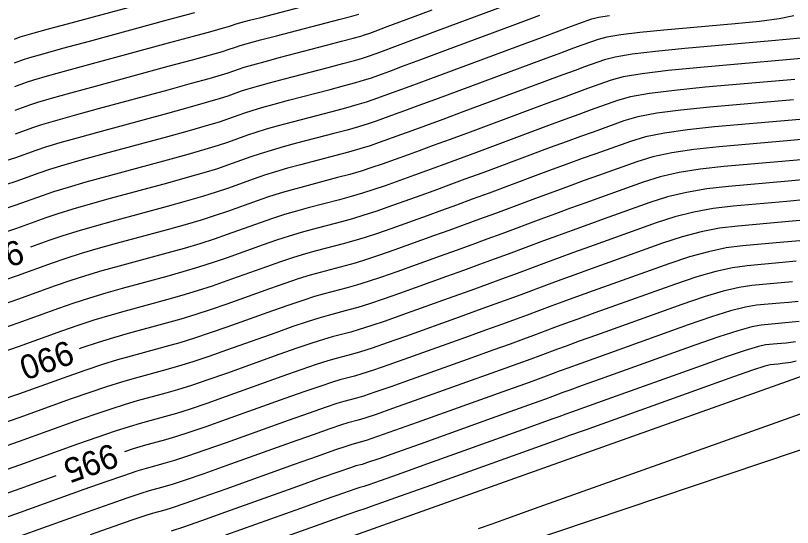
# Model space of a CAD drawing. Extents: x 2175772 to 2185556, y 721391 to 722853.
# Drawn here: x 2179071.3 to 2179161.1, y 721918.3 to 721977.4 of the extents above; entities that cross this region are included whole.
import ezdxf

# ---------------------------------------------------------------- set-up
doc = ezdxf.new("R2010")
doc.units = 0
for name, color, linetype in [('DT_X_Contour_Major', 7, 'Continuous'), ('DT_X_Contour_Minor', 7, 'Continuous'), ('DT_X_TIN_Hull', 7, 'Continuous')]:
    doc.layers.add(name, color=color, linetype=linetype)

msp = doc.modelspace()

# ---------------------------------------------------------------- linework, layer by layer
at = {"layer": 'DT_X_Contour_Major'}
for points in [[(2179071.294, 721963.77), (2179073.312, 721964.492), (2179074.353, 721964.832), (2179075.959, 721965.309), (2179078.132, 721965.922), (2179080.872, 721966.673), (2179088.932, 721968.858), (2179091.632, 721969.595), (2179093.69, 721970.167), (2179095.103, 721970.575), (2179095.873, 721970.818), (2179097.069, 721971.246), (2179097.71, 721971.451), (2179098.733, 721971.746), (2179100.141, 721972.129), (2179101.932, 721972.603), (2179107.219, 721973.983), (2179108.981, 721974.447), (2179110.304, 721974.8), (2179111.187, 721975.044), (2179111.629, 721975.179), (2179112.223, 721975.391), (2179112.842, 721975.619), (2179114.252, 721976.141), (2179116.453, 721976.959), (2179119.446, 721978.073)], [(2179162.018, 721974.797), (2179158.678, 721974.486), (2179148.637, 721973.601), (2179145.233, 721973.272), (2179142.554, 721972.948), (2179140.599, 721972.629), (2179139.368, 721972.315), (2179137.052, 721971.486), (2179135.964, 721971.092), (2179134.44, 721970.532), (2179132.479, 721969.807), (2179130.08, 721968.916), (2179123.102, 721966.319), (2179120.69, 721965.423), (2179118.689, 721964.683), (2179117.098, 721964.1), (2179115.917, 721963.673), (2179113.317, 721962.741), (2179112.272, 721962.386), (2179111.088, 721962.018), (2179109.765, 721961.637), (2179108.303, 721961.243), (2179104.218, 721960.176), (2179102.734, 721959.775), (2179101.346, 721959.37), (2179100.054, 721958.963), (2179098.858, 721958.554), (2179095.795, 721957.457), (2179094.498, 721957.018), (2179092.905, 721956.524), (2179091.014, 721955.974), (2179088.827, 721955.369), (2179082.598, 721953.68), (2179080.381, 721953.064), (2179078.401, 721952.482), (2179076.659, 721951.935), (2179075.154, 721951.421), (2179073.027, 721950.66)], [(2179163.731, 721963.251), (2179160.871, 721962.993), (2179152.599, 721962.264), (2179149.678, 721961.951), (2179147.119, 721961.558), (2179144.922, 721961.085), (2179143.087, 721960.533), (2179138.677, 721958.954), (2179136.999, 721958.35), (2179135.273, 721957.722), (2179133.5, 721957.071), (2179131.678, 721956.396), (2179126.757, 721954.565), (2179124.927, 721953.886), (2179123.125, 721953.225), (2179121.354, 721952.581), (2179119.611, 721951.954), (2179115.004, 721950.304), (2179113.357, 721949.727), (2179111.872, 721949.235), (2179110.549, 721948.827), (2179109.387, 721948.502), (2179106.505, 721947.75), (2179105.328, 721947.42), (2179103.959, 721946.995), (2179102.399, 721946.476), (2179100.646, 721945.861), (2179095.717, 721944.097), (2179093.894, 721943.462), (2179092.12, 721942.881), (2179090.396, 721942.353), (2179088.722, 721941.879), (2179084.324, 721940.687), (2179082.629, 721940.206), (2179080.842, 721939.656), (2179078.964, 721939.037), (2179078.651, 721938.928)], [(2179161.915, 721951.409), (2179160.094, 721951.239), (2179155.288, 721950.815), (2179153.406, 721950.567), (2179151.365, 721950.14), (2179149.165, 721949.534), (2179146.805, 721948.75), (2179140.302, 721946.422), (2179138.033, 721945.608), (2179136.107, 721944.912), (2179134.521, 721944.335), (2179133.276, 721943.876), (2179130.413, 721942.811), (2179129.163, 721942.35), (2179127.562, 721941.767), (2179125.609, 721941.062), (2179123.305, 721940.235), (2179116.691, 721937.867), (2179114.442, 721937.069), (2179112.656, 721936.452), (2179111.332, 721936.017), (2179110.471, 721935.762), (2179108.791, 721935.323), (2179107.922, 721935.065), (2179106.572, 721934.62), (2179104.743, 721933.988), (2179102.435, 721933.169), (2179095.639, 721930.736), (2179093.289, 721929.905), (2179091.335, 721929.237), (2179089.778, 721928.732), (2179088.617, 721928.39), (2179086.05, 721927.694), (2179084.877, 721927.347), (2179083.898, 721927.029)], [(2179161.41, 721939.711), (2179160.871, 721939.645), (2179160.342, 721939.585), (2179159.824, 721939.531), (2179159.316, 721939.484), (2179157.976, 721939.365), (2179157.134, 721939.182), (2179155.611, 721938.722), (2179153.407, 721937.984), (2179150.524, 721936.968), (2179139.068, 721932.866), (2179135.542, 721931.599), (2179134.875, 721931.356), (2179134.069, 721931.056), (2179133.4, 721930.813), (2179129.865, 721929.543), (2179118.378, 721925.43), (2179115.527, 721924.411), (2179113.44, 721923.67), (2179112.116, 721923.207), (2179111.555, 721923.021), (2179111.078, 721922.896), (2179110.515, 721922.71), (2179109.185, 721922.245), (2179107.088, 721921.5), (2179104.223, 721920.477), (2179095.561, 721917.376)], [(2179075.97, 721924.253), (2179071.784, 721922.755), (2179069.361, 721921.896)]]:
    msp.add_lwpolyline(points, dxfattribs=at)
at = {"layer": 'DT_X_Contour_Minor'}
for points in [[(2179071.163, 721974.707), (2179071.84, 721974.949), (2179072.372, 721975.113), (2179073.461, 721975.422), (2179075.108, 721975.877), (2179077.312, 721976.477), (2179088.895, 721979.617)], [(2179070.229, 721960.668), (2179071.326, 721961.035), (2179073.681, 721961.878), (2179074.814, 721962.252), (2179076.448, 721962.743), (2179078.582, 721963.351), (2179081.217, 721964.074), (2179088.911, 721966.16), (2179091.509, 721966.871), (2179093.533, 721967.439), (2179094.982, 721967.864), (2179095.858, 721968.146), (2179097.427, 721968.707), (2179098.179, 721968.954), (2179099.256, 721969.271), (2179100.659, 721969.659), (2179102.389, 721970.117), (2179107.435, 721971.435), (2179109.138, 721971.885), (2179110.461, 721972.244), (2179111.404, 721972.512), (2179111.967, 721972.691), (2179112.962, 721973.048), (2179113.693, 721973.315), (2179115.139, 721973.85), (2179120.177, 721975.722), (2179128.802, 721978.932)], [(2179071.228, 721969.238), (2179072.576, 721969.721), (2179073.43, 721969.991), (2179074.983, 721970.439), (2179077.233, 721971.066), (2179080.181, 721971.87), (2179088.974, 721974.254), (2179091.88, 721975.043), (2179094.003, 721975.625), (2179095.345, 721975.997), (2179095.905, 721976.162), (2179096.354, 721976.323), (2179096.686, 721976.424), (2179097.346, 721976.606), (2179098.332, 721976.87), (2179099.646, 721977.215), (2179106.542, 721979.016)], [(2179161.241, 721977.404), (2179159.522, 721977.055), (2179157.256, 721976.738), (2179154.444, 721976.451), (2179146.218, 721975.725), (2179143.43, 721975.455), (2179141.235, 721975.19), (2179139.633, 721974.929), (2179138.625, 721974.672), (2179136.727, 721973.992), (2179135.757, 721973.64), (2179134.273, 721973.094), (2179132.274, 721972.354), (2179119.843, 721967.73), (2179117.801, 721966.975), (2179116.247, 721966.404), (2179115.178, 721966.016), (2179112.979, 721965.229), (2179112.055, 721964.917), (2179110.931, 721964.574), (2179109.608, 721964.199), (2179108.086, 721963.791), (2179103.761, 721962.661), (2179102.216, 721962.246), (2179100.824, 721961.845), (2179099.585, 721961.461), (2179098.5, 721961.092), (2179095.811, 721960.129), (2179094.619, 721959.73), (2179093.062, 721959.253), (2179091.138, 721958.698), (2179088.848, 721958.066), (2179082.253, 721956.279), (2179079.931, 721955.636), (2179077.913, 721955.047), (2179076.197, 721954.514), (2179074.785, 721954.036), (2179071.424, 721952.833), (2179070.043, 721952.36)], [(2179070.105, 721955.129), (2179071.392, 721955.567), (2179074.417, 721956.65), (2179075.736, 721957.094), (2179077.424, 721957.613), (2179079.481, 721958.207), (2179081.907, 721958.877), (2179088.869, 721960.764), (2179091.261, 721961.422), (2179093.219, 721961.981), (2179094.74, 721962.441), (2179095.827, 721962.801), (2179098.142, 721963.631), (2179099.116, 721963.959), (2179100.301, 721964.321), (2179101.697, 721964.717), (2179103.304, 721965.147), (2179107.869, 721966.339), (2179109.451, 721966.761), (2179110.774, 721967.131), (2179111.838, 721967.449), (2179112.642, 721967.716), (2179114.44, 721968.36), (2179115.395, 721968.707), (2179116.914, 721969.267), (2179118.995, 721970.038), (2179129.441, 721973.924), (2179132.07, 721974.901), (2179134.107, 721975.656), (2179135.55, 721976.189), (2179136.402, 721976.498), (2179137.881, 721977.028), (2179138.667, 721977.228), (2179139.915, 721977.432)], [(2179070.167, 721957.899), (2179071.359, 721958.301), (2179074.049, 721959.264), (2179075.275, 721959.673), (2179076.936, 721960.178), (2179079.032, 721960.779), (2179081.562, 721961.476), (2179088.89, 721963.462), (2179091.385, 721964.147), (2179093.376, 721964.71), (2179094.861, 721965.152), (2179095.842, 721965.474), (2179097.785, 721966.169), (2179098.647, 721966.456), (2179099.779, 721966.796), (2179101.178, 721967.188), (2179102.846, 721967.632), (2179107.652, 721968.887), (2179109.295, 721969.323), (2179110.618, 721969.687), (2179111.621, 721969.981), (2179112.304, 721970.204), (2179113.701, 721970.704), (2179114.544, 721971.011), (2179116.026, 721971.558), (2179118.148, 721972.345), (2179120.908, 721973.371), (2179129.121, 721976.428), (2179131.866, 721977.448)], [(2179071.195, 721971.973), (2179072.208, 721972.335), (2179072.969, 721972.57), (2179074.494, 721973.004), (2179076.783, 721973.637), (2179079.836, 721974.469), (2179088.994, 721976.952), (2179092.003, 721977.768)], [(2179071.261, 721966.504), (2179072.944, 721967.107), (2179073.892, 721967.411), (2179075.471, 721967.874), (2179077.683, 721968.494), (2179080.526, 721969.272), (2179088.953, 721971.556), (2179091.756, 721972.319), (2179093.846, 721972.896), (2179095.224, 721973.286), (2179095.889, 721973.49), (2179096.712, 721973.784), (2179097.241, 721973.949), (2179098.211, 721974.221), (2179099.622, 721974.6), (2179101.474, 721975.088), (2179108.825, 721977.008), (2179110.147, 721977.357), (2179110.97, 721977.576)], [(2179165.129, 721972.718), (2179150.448, 721971.424), (2179146.695, 721971.058), (2179143.722, 721970.692), (2179141.527, 721970.326), (2179140.112, 721969.959), (2179137.377, 721968.979), (2179136.171, 721968.543), (2179134.607, 721967.97), (2179132.683, 721967.26), (2179130.4, 721966.412), (2179123.833, 721963.968), (2179121.537, 721963.116), (2179119.576, 721962.392), (2179117.949, 721961.796), (2179116.656, 721961.329), (2179113.654, 721960.254), (2179112.489, 721959.854), (2179111.245, 721959.461), (2179109.922, 721959.075), (2179108.52, 721958.695), (2179104.676, 721957.691), (2179103.253, 721957.304), (2179101.869, 721956.895), (2179100.523, 721956.466), (2179099.216, 721956.015), (2179095.78, 721954.785), (2179094.378, 721954.307), (2179092.748, 721953.795), (2179090.891, 721953.25), (2179088.806, 721952.671), (2179082.943, 721951.081), (2179080.83, 721950.492), (2179078.889, 721949.917), (2179077.12, 721949.355), (2179075.522, 721948.807), (2179071.49, 721947.364), (2179069.919, 721946.821)], [(2179161.338, 721970.046), (2179150.986, 721969.134), (2179147.441, 721968.781), (2179144.571, 721968.409), (2179142.376, 721968.016), (2179140.856, 721967.602), (2179137.702, 721966.473), (2179136.378, 721965.995), (2179134.773, 721965.408), (2179132.887, 721964.712), (2179130.719, 721963.908), (2179124.564, 721961.617), (2179122.385, 721960.808), (2179120.463, 721960.1), (2179118.8, 721959.492), (2179117.395, 721958.985), (2179113.992, 721957.766), (2179112.706, 721957.322), (2179111.402, 721956.905), (2179110.078, 721956.513), (2179108.736, 721956.147), (2179105.133, 721955.205), (2179103.772, 721954.833), (2179102.392, 721954.42), (2179100.992, 721953.968), (2179099.573, 721953.477), (2179095.764, 721952.113), (2179094.257, 721951.596), (2179092.591, 721951.067), (2179090.767, 721950.526), (2179088.785, 721949.973), (2179083.288, 721948.483), (2179081.28, 721947.921), (2179079.378, 721947.352), (2179077.581, 721946.776), (2179075.89, 721946.193), (2179071.522, 721944.63), (2179069.857, 721944.052)], [(2179161.183, 721967.695), (2179151.523, 721966.844), (2179148.186, 721966.505), (2179145.42, 721966.125), (2179143.224, 721965.705), (2179141.599, 721965.246), (2179138.027, 721963.967), (2179136.585, 721963.447), (2179134.94, 721962.846), (2179133.091, 721962.165), (2179131.039, 721961.404), (2179125.295, 721959.266), (2179123.232, 721958.501), (2179121.351, 721957.808), (2179119.651, 721957.189), (2179118.134, 721956.641), (2179114.329, 721955.279), (2179112.923, 721954.791), (2179111.558, 721954.348), (2179110.235, 721953.951), (2179108.953, 721953.598), (2179105.59, 721952.72), (2179104.291, 721952.362), (2179102.914, 721951.945), (2179101.461, 721951.471), (2179099.931, 721950.938), (2179095.748, 721949.441), (2179094.136, 721948.884), (2179092.434, 721948.338), (2179090.643, 721947.801), (2179088.764, 721947.275), (2179083.633, 721945.884), (2179081.73, 721945.349), (2179079.866, 721944.786), (2179078.042, 721944.196), (2179076.258, 721943.579), (2179071.555, 721941.895), (2179069.795, 721941.282)], [(2179164.08, 721965.618), (2179161.027, 721965.344), (2179152.061, 721964.554), (2179148.932, 721964.228), (2179146.269, 721963.841), (2179144.073, 721963.395), (2179142.343, 721962.889), (2179138.352, 721961.46), (2179136.792, 721960.898), (2179135.107, 721960.284), (2179133.295, 721959.618), (2179131.359, 721958.9), (2179126.026, 721956.915), (2179124.079, 721956.194), (2179122.238, 721955.517), (2179120.502, 721954.885), (2179118.872, 721954.298), (2179114.666, 721952.792), (2179113.14, 721952.259), (2179111.715, 721951.791), (2179110.392, 721951.389), (2179109.17, 721951.05), (2179106.047, 721950.235), (2179104.809, 721949.891), (2179103.437, 721949.47), (2179101.93, 721948.973), (2179100.289, 721948.4), (2179095.733, 721946.769), (2179094.015, 721946.173), (2179092.277, 721945.609), (2179090.52, 721945.077), (2179088.743, 721944.577), (2179083.979, 721943.286), (2179082.179, 721942.777), (2179080.354, 721942.221), (2179078.503, 721941.617), (2179076.627, 721940.964), (2179071.588, 721939.161), (2179069.733, 721938.513)], [(2179163.381, 721960.885), (2179160.716, 721960.642), (2179153.137, 721959.974), (2179150.423, 721959.674), (2179147.968, 721959.274), (2179145.77, 721958.775), (2179143.83, 721958.176), (2179139.002, 721956.447), (2179137.206, 721955.801), (2179135.44, 721955.16), (2179133.704, 721954.524), (2179131.998, 721953.892), (2179127.488, 721952.214), (2179125.774, 721951.579), (2179124.013, 721950.934), (2179122.205, 721950.277), (2179120.35, 721949.61), (2179115.341, 721947.817), (2179113.574, 721947.196), (2179112.029, 721946.678), (2179110.705, 721946.265), (2179109.604, 721945.954), (2179106.962, 721945.264), (2179105.847, 721944.949), (2179104.482, 721944.52), (2179102.868, 721943.978), (2179101.004, 721943.323), (2179095.702, 721941.425), (2179093.773, 721940.751), (2179091.963, 721940.152), (2179090.272, 721939.629), (2179088.701, 721939.181), (2179084.669, 721938.088), (2179083.079, 721937.634), (2179081.331, 721937.09), (2179079.426, 721936.458), (2179077.363, 721935.736), (2179071.653, 721933.692), (2179069.609, 721932.974)], [(2179163.032, 721958.518), (2179160.56, 721958.291), (2179153.674, 721957.684), (2179151.169, 721957.397), (2179148.817, 721956.991), (2179146.619, 721956.465), (2179144.574, 721955.82), (2179139.327, 721953.941), (2179137.413, 721953.253), (2179135.607, 721952.598), (2179133.908, 721951.976), (2179132.318, 721951.388), (2179128.22, 721949.863), (2179126.621, 721949.272), (2179124.9, 721948.642), (2179123.056, 721947.973), (2179121.089, 721947.266), (2179115.679, 721945.329), (2179113.791, 721944.664), (2179112.186, 721944.122), (2179110.862, 721943.703), (2179109.821, 721943.406), (2179107.419, 721942.779), (2179106.365, 721942.478), (2179105.005, 721942.045), (2179103.337, 721941.481), (2179101.362, 721940.785), (2179095.686, 721938.753), (2179093.652, 721938.039), (2179091.806, 721937.423), (2179090.149, 721936.905), (2179088.68, 721936.483), (2179085.014, 721935.49), (2179083.528, 721935.062), (2179081.819, 721934.525), (2179079.887, 721933.878), (2179077.731, 721933.122), (2179071.686, 721930.958), (2179069.547, 721930.205)], [(2179162.682, 721956.151), (2179160.405, 721955.941), (2179154.212, 721955.395), (2179151.915, 721955.12), (2179149.666, 721954.707), (2179147.467, 721954.155), (2179145.318, 721953.463), (2179139.652, 721951.435), (2179137.62, 721950.705), (2179135.773, 721950.036), (2179134.112, 721949.429), (2179132.637, 721948.884), (2179128.951, 721947.512), (2179127.469, 721946.964), (2179125.787, 721946.35), (2179123.907, 721945.67), (2179121.827, 721944.923), (2179116.016, 721942.842), (2179114.008, 721942.133), (2179112.342, 721941.565), (2179111.019, 721941.141), (2179110.037, 721940.858), (2179107.877, 721940.294), (2179106.884, 721940.007), (2179105.527, 721939.57), (2179103.806, 721938.983), (2179101.719, 721938.246), (2179095.67, 721936.081), (2179093.531, 721935.328), (2179091.649, 721934.695), (2179090.025, 721934.18), (2179088.659, 721933.786), (2179085.36, 721932.891), (2179083.978, 721932.491), (2179082.307, 721931.96), (2179080.348, 721931.299), (2179078.099, 721930.507), (2179071.719, 721928.224), (2179069.485, 721927.435)], [(2179162.333, 721953.784), (2179160.249, 721953.59), (2179154.75, 721953.105), (2179152.66, 721952.843), (2179150.515, 721952.423), (2179148.316, 721951.845), (2179146.062, 721951.107), (2179139.977, 721948.928), (2179137.827, 721948.156), (2179135.94, 721947.474), (2179134.317, 721946.882), (2179132.957, 721946.38), (2179129.682, 721945.161), (2179128.316, 721944.657), (2179126.675, 721944.059), (2179124.758, 721943.366), (2179122.566, 721942.579), (2179116.354, 721940.354), (2179114.225, 721939.601), (2179112.499, 721939.009), (2179111.175, 721938.579), (2179110.254, 721938.31), (2179108.334, 721937.808), (2179107.403, 721937.536), (2179106.05, 721937.095), (2179104.274, 721936.486), (2179102.077, 721935.708), (2179095.655, 721933.408), (2179093.41, 721932.617), (2179091.492, 721931.966), (2179089.902, 721931.456), (2179088.638, 721931.088), (2179085.705, 721930.292), (2179084.428, 721929.919), (2179082.796, 721929.394), (2179080.809, 721928.719), (2179078.468, 721927.893), (2179071.751, 721925.489), (2179069.423, 721924.666)], [(2179161.497, 721949.033), (2179159.938, 721948.888), (2179155.825, 721948.525), (2179154.151, 721948.29), (2179152.214, 721947.856), (2179150.013, 721947.224), (2179147.549, 721946.394), (2179140.627, 721943.915), (2179138.24, 721943.059), (2179136.273, 721942.35), (2179134.725, 721941.788), (2179133.596, 721941.372), (2179131.144, 721940.46), (2179130.011, 721940.043), (2179128.45, 721939.475), (2179126.461, 721938.758), (2179124.044, 721937.891), (2179117.029, 721935.379), (2179114.659, 721934.538), (2179112.813, 721933.896), (2179111.489, 721933.455), (2179110.688, 721933.214), (2179109.249, 721932.838), (2179108.44, 721932.594), (2179107.095, 721932.145), (2179105.212, 721931.491), (2179102.793, 721930.631), (2179095.623, 721928.064), (2179093.168, 721927.194), (2179091.178, 721926.509), (2179089.654, 721926.008), (2179088.596, 721925.692), (2179086.395, 721925.095), (2179085.327, 721924.776), (2179083.772, 721924.264), (2179081.731, 721923.56), (2179079.204, 721922.665), (2179071.817, 721920.021), (2179069.3, 721919.127)], [(2179161.079, 721946.658), (2179159.783, 721946.537), (2179156.363, 721946.235), (2179154.897, 721946.013), (2179153.063, 721945.573), (2179150.862, 721944.914), (2179148.293, 721944.038), (2179138.447, 721940.511), (2179136.44, 721939.788), (2179134.929, 721939.241), (2179133.916, 721938.868), (2179131.875, 721938.109), (2179130.858, 721937.735), (2179129.337, 721937.184), (2179127.312, 721936.455), (2179117.366, 721932.892), (2179114.876, 721932.006), (2179112.969, 721931.339), (2179111.646, 721930.893), (2179110.905, 721930.665), (2179109.706, 721930.352), (2179108.959, 721930.123), (2179107.618, 721929.67), (2179105.681, 721928.993), (2179103.15, 721928.092), (2179095.608, 721925.392), (2179093.047, 721924.483), (2179091.021, 721923.78), (2179089.531, 721923.284), (2179088.575, 721922.994), (2179086.741, 721922.497), (2179085.777, 721922.204), (2179084.261, 721921.699), (2179082.192, 721920.981), (2179079.572, 721920.051), (2179071.849, 721917.286)], [(2179161.715, 721944.392), (2179160.66, 721944.282), (2179159.627, 721944.186), (2179156.901, 721943.945), (2179155.643, 721943.736), (2179153.912, 721943.289), (2179151.71, 721942.604), (2179149.036, 721941.681), (2179138.654, 721937.963), (2179136.607, 721937.226), (2179135.134, 721936.693), (2179134.235, 721936.364), (2179132.606, 721935.758), (2179131.705, 721935.428), (2179130.224, 721934.892), (2179128.163, 721934.151), (2179117.703, 721930.405), (2179115.093, 721929.474), (2179113.126, 721928.783), (2179111.802, 721928.331), (2179111.121, 721928.117), (2179110.163, 721927.867), (2179109.478, 721927.652), (2179108.14, 721927.195), (2179106.15, 721926.496), (2179103.508, 721925.554), (2179095.592, 721922.72), (2179092.926, 721921.772), (2179090.864, 721921.051), (2179089.407, 721920.56), (2179088.554, 721920.296), (2179087.086, 721919.898), (2179086.226, 721919.632), (2179084.749, 721919.133), (2179082.654, 721918.401), (2179079.941, 721917.436)], [(2179181.624, 721942.699), (2179160.992, 721935.351), (2179137.395, 721926.947), (2179107.533, 721916.311), (2179097.444, 721912.717), (2179088.467, 721909.504), (2179088.025, 721909.346), (2179086.702, 721908.872), (2179084.498, 721908.083), (2179081.414, 721906.979), (2179072.013, 721903.615), (2179068.928, 721902.51)], [(2179161.831, 721942.079), (2179161.029, 721941.988), (2179160.242, 721941.907), (2179159.472, 721941.835), (2179157.439, 721941.655), (2179156.388, 721941.459), (2179154.762, 721941.005), (2179152.559, 721940.294), (2179149.78, 721939.325), (2179138.861, 721935.414), (2179136.773, 721934.664), (2179135.338, 721934.146), (2179134.555, 721933.86), (2179133.338, 721933.407), (2179132.553, 721933.121), (2179131.112, 721932.601), (2179126.26, 721930.86), (2179118.041, 721927.917), (2179115.31, 721926.943), (2179113.283, 721926.226), (2179111.959, 721925.769), (2179111.338, 721925.569), (2179110.621, 721925.382), (2179109.997, 721925.181), (2179108.663, 721924.72), (2179106.619, 721923.998), (2179103.866, 721923.016), (2179095.577, 721920.048), (2179092.805, 721919.06), (2179090.707, 721918.323), (2179089.283, 721917.835)], [(2179161.491, 721937.501), (2179160.872, 721937.332), (2179159.911, 721937.21), (2179159.656, 721937.181), (2179159.406, 721937.155), (2179158.514, 721937.076), (2179157.879, 721936.906), (2179156.46, 721936.438), (2179154.256, 721935.674), (2179151.267, 721934.612), (2179137.106, 721929.54), (2179135.194, 721928.852), (2179134.8, 721928.706), (2179132.886, 721928.017), (2179118.716, 721922.942), (2179115.744, 721921.879), (2179113.597, 721921.113), (2179112.272, 721920.645), (2179111.772, 721920.473), (2179111.535, 721920.411), (2179111.034, 721920.239), (2179109.708, 721919.77), (2179107.557, 721919.003), (2179092.563, 721913.638)], [(2179162.514, 721931.544), (2179150.171, 721927.157), (2179140.868, 721923.844), (2179131.768, 721920.611), (2179129.837, 721919.925), (2179128.024, 721919.28), (2179126.332, 721918.678), (2179124.759, 721918.118)]]:
    msp.add_lwpolyline(points, dxfattribs=at)
at = {"layer": 'DT_X_TIN_Hull'}
msp.add_lwpolyline([(2178979.881, 721865.982), (2179003.576, 721873.952), (2179027.271, 721881.923), (2179050.967, 721889.893), (2179074.662, 721897.864), (2179098.357, 721905.834), (2179122.052, 721913.804), (2179145.747, 721921.775), (2179169.442, 721929.745)], dxfattribs=at)

# ---------------------------------------------------------------- texts
at = {"layer": 'DT_X_Contour_Major'}
for s, rotation, p in [('985', 197.82025, (2179071.681, 721951.609)), ('990', 199.55405, (2179077.382, 721939.967)), ('995', 199.29565, (2179082.512, 721928.053))]:
    msp.add_text(s, height=2.8, rotation=rotation, dxfattribs=at).set_placement(p)

doc.saveas('drawing.dxf')
